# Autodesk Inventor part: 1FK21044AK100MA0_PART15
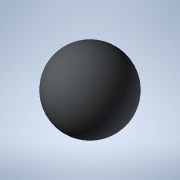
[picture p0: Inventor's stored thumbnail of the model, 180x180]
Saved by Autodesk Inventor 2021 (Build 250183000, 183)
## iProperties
Created: 2025-04
Part Number: 1FK21044AK100MA0_PART15
Material: Generic
Catalog Web Link: www.3dfindit.com
Description: -Servo synchronous motor
Document SubType Name: Modeling
Designer: psAdmin
Mass: 0.137258 g
Surface Area: 1.2868 cm^2
Volume: 0.137258 cm^3
Density: 1 g/cm^3
Appearance: PSOLRGB-212-217-219
Category: PARTsolutions
Title: 1FK21044AK100MA0_PART15
Author: Cadenas PARTsolutions
Comments: Servo synchronous motor
Sending System: PARTsolutions
Preprocessor: ST-DEVELOPER v19.3
PSOL_IDENT_0: {$CADENAS_DATA/23d-libs/siemens_ag/_cat_/5e/d8/1fk21044ak100ma0.prj},216 {VTYP=3D},{NB=1FK21044AK100
PSOL_IDENT_1: MA0_PART15},{LINA=1FK21044AK100MA0_PART15},{NN=1FK21044AK100MA0_PART15},{NOPRJ=TRUE},{DATE=19.08.202
PSOL_IDENT_2: 5 14:00:41},{GEOMDATE=30.07.2025 02:00:53},{VERSION=},{LINEID=10},{WBVAR=},{WBNUMERIC=}  {NB=1FK2104
PSOL_IDENT_3: 4AK100MA0_PART15},{LINA=1FK21044AK100MA0_PART15},{KT=DUMMY},{PREVIEW=../../../_pool_/cb/72/p_d211_xx
PSOL_IDENT_4: _00434j.png},{DESCSHORT=SIMOTICS S-1FK2 HD, SINAMICS S210 3AC 400V-480V, 0.95 Nm, 6000 rpm},{DESCLON
PSOL_IDENT_5: G=SIMOTICS S-1FK2 HD servo motor M0=1.27 Nm; PN = 0.6 kW at nN=6000 rpm (380-480 V); PN = 0.4 kW at
PSOL_IDENT_6: nN=3000 rpm (200-240 V); with holding brake; degree of protection IP64; cylindrical shaft D19x40mm;
PSOL_IDENT_7: absolute encoder 22-bit + 12-bit multiturn (encoder AM22DQC); with OCC interface; plug size M17, rot
PSOL_IDENT_8: atable; SIMOTICS S-1FK2 servomotorfor a wide range of uses in industrial environments. SIMOTICS S‑1F
PSOL_IDENT_9: K2 servomotors are compact synchronous motors with a high dynamic performance that set themselves ap
PSOL_IDENT_10: art as a result of their high power density, degree of protection and overload capability. The motor
PSOL_IDENT_11: s are available in two variants: as High Dynamic variant (highest dynamic performance as a result of
PSOL_IDENT_12: the low intrinsic moment of inertia for applications demanding a high dynamic performance with low
PSOL_IDENT_13: moved masses) - and as Compact variant (precise and stable closed-loop control for medium up to larg
PSOL_IDENT_14: e moved masses as a result of a medium intrinsic moment of inertia). SIMOTICSS‑1FK2 servomotors full
PSOL_IDENT_15: y exploit their strengths in a system with the SINAMICSS210 frequency converter and simple connectio
PSOL_IDENT_16: n using the one cable connection (OCC). Advantages include the short control and positioning times,
PSOL_IDENT_17: fast and precise correction of disturbing quantities as well as stable control with a high dynamic p
PSOL_IDENT_18: erformance. The servo motors can be configured to address a wide range of requirements. For example
PSOL_IDENT_19: with and without holding brake, IP64 or IP65 degree of protection, singleturn or multiturn absolute
PSOL_IDENT_20: encoders - to name just a few. Further, the servomotors are available in different shaft heights ext
PSOL_IDENT_21: ending from 20 to 100. A shaft sealing ring is available to achieve an IP65 degree of protection and
PSOL_IDENT_22: for subsequent mounting at the motor or as spare part. SIMOTICS - the optimum motor for each and ev
PSOL_IDENT_23: ery motion control application.},{INTNO=804766910005},{SUPPLIERALTNO=1FK2104-4AK10-0MA0},{MANUID=1FK
PSOL_IDENT_24: 21044AK100MA0},{MANUNAME=Siemens},{MANUTYPEDESC=Synchronous motor 1FK2-HD 1,27 Nm},{AAU732=SIMOTICS}
PSOL_IDENT_25: ,{AAO057=S-1FK2},{AAU734=SIMOTICS S-1FK2 HD servo motor M0=1.27 Nm; PN = 0.6 kW at nN=6000 rpm (380-
PSOL_IDENT_26: 480 V); PN = 0.4 kW at nN=3000 rpm (200-240 V); with holding brake; degree of protection IP64; cylin
PSOL_IDENT_27: drical shaft D19x40mm; absolute encoder 22-bit + 12-bit multiturn (encoder AM22DQC); with OCC interf
PSOL_IDENT_28: ace; plug size M17, rotatable;},{AAW338=Synchronous motor 1FK2-HD 1,27 Nm},{AAO742=SIMOTICS},{AAO663=
PSOL_IDENT_29: 4042948691076},{NOCUPEROU=1},{PRICEQUANTITY=1},{QUANTITYMIN=1},{QUANTITYINT=1},{CTN=85015100},{COO=D
PSOL_IDENT_30: E},{AAO676=1FK2104-4AK10-0MA0},{AAO677=Siemens AG},{ORDERUNIT=C62},{CONTENTUNIT=C62}
NB: 1FK21044AK100MA0_PART15
NT: Servo synchronous motor
NBSYN: $MANUID._PART15
LINA: 1FK21044AK100MA0_PART15
CATALOG: SIEMENS
PREVIEW: ../../../_pool_/cb/72/p_d211_xx_00434j.png
DESCSHORT: SIMOTICS S-1FK2 HD, SINAMICS S210 3AC 400V-480V, 0.95 Nm, 6000 rpm
DESCLONG: SIMOTICS S-1FK2 HD servo motor M0=1.27 Nm; PN = 0.6 kW at nN=6000 rpm (380-480 V); PN = 0.4 kW at nN=3000 rpm (200-240 V); with holding brake; degree of protect
INTNO: 804766910005
SUPPLIERALTNO: 1FK2104-4AK10-0MA0
MANUID: 1FK21044AK100MA0
MANUNAME: Siemens
MANUTYPEDESC: Synchronous motor 1FK2-HD 1,27 Nm
AAU732: SIMOTICS
AAO057: S-1FK2
AAU734: SIMOTICS S-1FK2 HD servo motor M0=1.27 Nm; PN = 0.6 kW at nN=6000 rpm (380-480 V); PN = 0.4 kW at nN=3000 rpm (200-240 V); with holding brake; degree of protect
AAW338: Synchronous motor 1FK2-HD 1,27 Nm
AAO742: SIMOTICS
AAO663: 4042948691076.0
NOCUPEROU: 1
PRICEQUANTITY: 1
QUANTITYMIN: 1
QUANTITYINT: 1
CTN: 85015100
COO: DE
ARTICLENO: 1FK21044AK100MA0_PART15
BOMINFO: 1FK21044AK100MA0_PART15
CREATOR: CADENAS GmbH
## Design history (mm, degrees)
feature "2025_04_17_15_35_41_0968"
body "Solid1"
